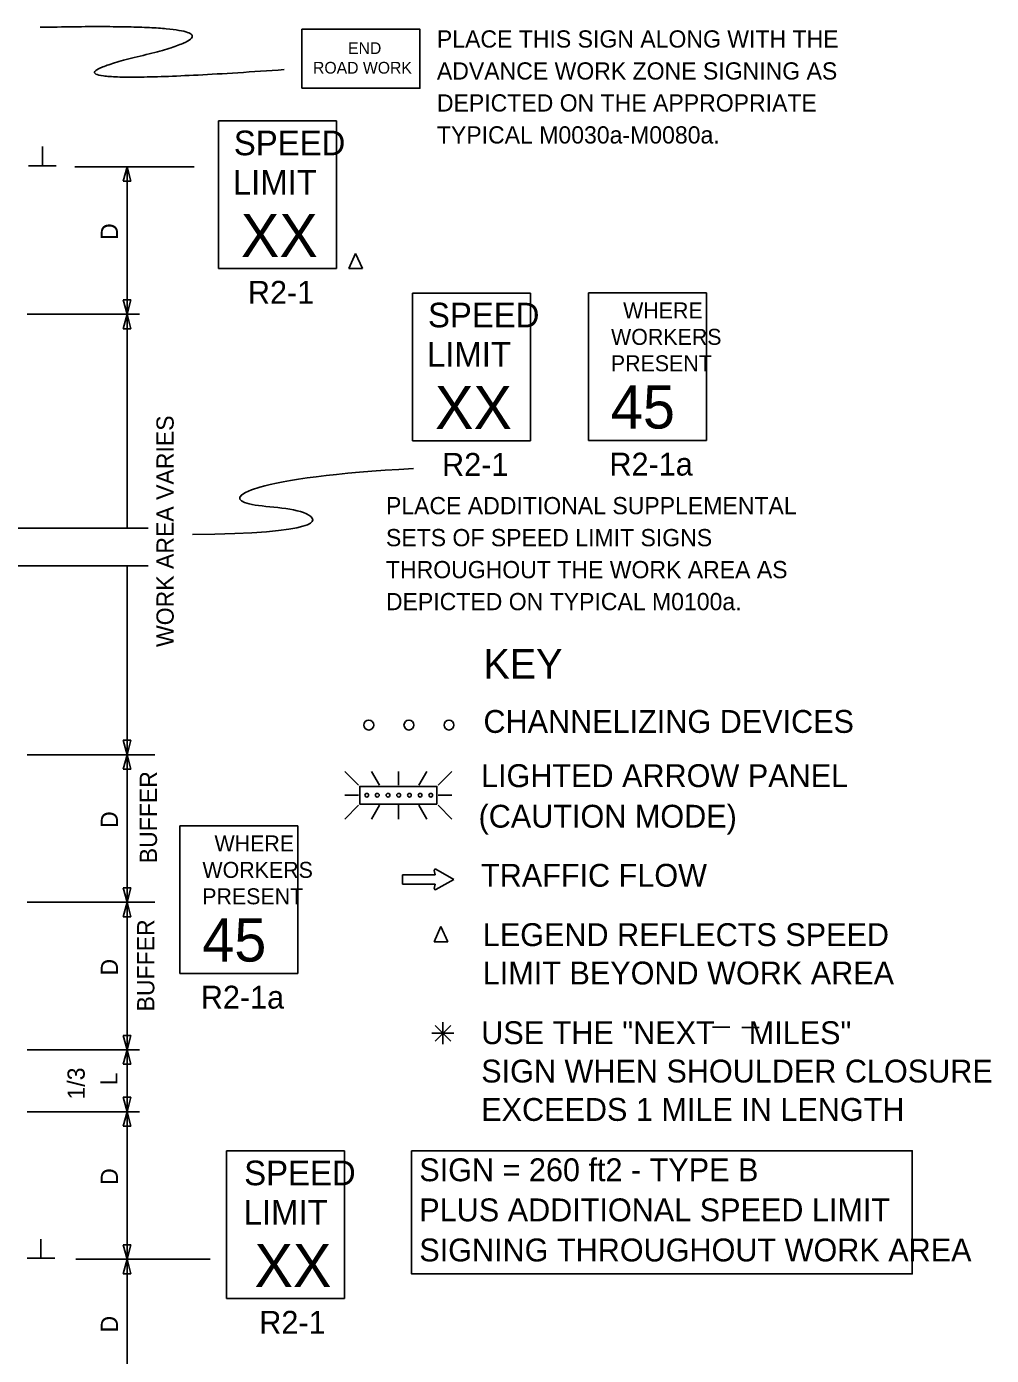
# Model space of a CAD drawing. Extents: x 16730 to 18471, y 6979 to 8225.
# Drawn here: x 17053 to 17445, y 7668 to 8208 of the extents above; entities that cross this region are included whole.
import ezdxf

# ---------------------------------------------------------------- set-up
doc = ezdxf.new("R2010")
doc.units = 0
for name, color, linetype in [('MT_SCRATCH_LEVEL_E', 7, 'Continuous'), ('TRAFFIC_SIGNS_PR', 7, 'Continuous'), ('TYPICAL_EX', 7, 'Continuous'), ('TYPICAL_TEXT_DIMEN_EX', 7, 'Continuous'), ('TYPICAL_TEXT_DIMEN_PR', 7, 'Continuous')]:
    doc.layers.add(name, color=color, linetype=linetype)

msp = doc.modelspace()

# ---------------------------------------------------------------- linework, layer by layer
at = {"layer": 'MT_SCRATCH_LEVEL_E'}
for p, q in [((17218.87, 7863.13), (17205.61, 7863.13)), ((17205.61, 7863.13), (17205.61, 7859.39)), ((17218.87, 7863.13), (17205.61, 7863.13)), ((17205.61, 7863.13), (17205.61, 7859.39)), ((17218.55, 7864.91), (17218.87, 7863.13)), ((17218.55, 7864.91), (17218.87, 7863.13)), ((17226.48, 7861.28), (17219.24, 7865.39)), ((17226.48, 7861.28), (17219.24, 7865.39)), ((17219.24, 7857.14), (17226.48, 7861.28)), ((17219.24, 7857.14), (17226.48, 7861.28)), ((17205.61, 7859.39), (17218.87, 7859.39)), ((17205.61, 7859.39), (17218.87, 7859.39)), ((17218.87, 7859.39), (17218.55, 7857.62)), ((17218.87, 7859.39), (17218.55, 7857.62))]:
    msp.add_line(p, q, dxfattribs=at)
for centre, start, end in [((17219.01, 7864.99), 60.4248, 189.9638), ((17219.01, 7864.99), 60.4248, 189.9638), ((17219.01, 7857.55), 170.0362, 299.7731), ((17219.01, 7857.55), 170.0362, 299.7731)]:
    msp.add_arc(centre, 0.463, start, end, dxfattribs=at)
at = {"layer": 'TRAFFIC_SIGNS_PR'}
for p, q in [((17130.75, 8169.59), (17178.75, 8169.59)), ((17130.75, 8109.59), (17130.75, 8169.59)), ((17178.75, 8109.59), (17178.75, 8169.59)), ((17130.75, 8109.59), (17178.75, 8109.59)), ((17209.69, 8099.63), (17257.69, 8099.63)), ((17209.69, 8039.63), (17209.69, 8099.63)), ((17257.69, 8039.63), (17257.69, 8099.63)), ((17281.19, 8099.74), (17329.19, 8099.74)), ((17281.19, 8039.74), (17281.19, 8099.74)), ((17329.19, 8039.74), (17329.19, 8099.74)), ((17209.69, 8039.63), (17257.69, 8039.63)), ((17281.19, 8039.74), (17329.19, 8039.74)), ((17182.12, 7905.19), (17187.76, 7899.55)), ((17196.3, 7899.55), (17193.04, 7905.19)), ((17203.93, 7899.55), (17203.93, 7905.19)), ((17212.2, 7899.55), (17215.46, 7905.19)), ((17220.1, 7899.55), (17225.74, 7905.2)), ((17187.76, 7895.49), (17182.12, 7895.49)), ((17191.03, 7895.49), (17191.03, 7895.49)), ((17195.38, 7895.49), (17195.38, 7895.49)), ((17199.73, 7895.49), (17199.73, 7895.49)), ((17204.08, 7895.49), (17204.08, 7895.49)), ((17208.42, 7895.49), (17208.42, 7895.49)), ((17212.77, 7895.49), (17212.77, 7895.49)), ((17217.12, 7895.49), (17217.12, 7895.49)), ((17220.1, 7895.49), (17225.74, 7895.49)), ((17182.12, 7885.79), (17187.76, 7891.43)), ((17192.99, 7885.79), (17196.25, 7891.43)), ((17203.93, 7891.43), (17203.93, 7885.79)), ((17215.51, 7885.79), (17212.25, 7891.43)), ((17220.1, 7891.43), (17225.74, 7885.78)), ((17115.04, 7883.05), (17163.04, 7883.05)), ((17115.04, 7823.05), (17115.04, 7883.05)), ((17163.04, 7823.05), (17163.04, 7883.05)), ((17115.04, 7823.05), (17163.04, 7823.05)), ((17134.04, 7750.86), (17182.04, 7750.86)), ((17134.04, 7690.86), (17134.04, 7750.86)), ((17182.04, 7690.86), (17182.04, 7750.86)), ((17134.04, 7690.86), (17182.04, 7690.86))]:
    msp.add_line(p, q, dxfattribs=at)
for points in [[(17164.73, 8182.91), (17212.73, 8182.91), (17212.73, 8206.91), (17164.73, 8206.91)], [(17219.64, 7891.89), (17188.22, 7891.89), (17188.22, 7899.09), (17219.64, 7899.09)]]:
    msp.add_lwpolyline(points, close=True, dxfattribs=at)
for points in [[(17186.57, 8115.76), (17183.77, 8109.59)], [(17183.77, 8109.59), (17186.57, 8115.76)], [(17189.36, 8109.59), (17186.57, 8115.76)], [(17186.57, 8115.76), (17189.36, 8109.59)], [(17183.77, 8109.59), (17189.36, 8109.59)], [(17189.36, 8109.59), (17183.77, 8109.59)], [(17221.24, 7842.11), (17218.45, 7835.94)], [(17218.45, 7835.94), (17221.24, 7842.11)], [(17224.04, 7835.94), (17221.24, 7842.11)], [(17221.24, 7842.11), (17224.04, 7835.94)], [(17218.45, 7835.94), (17224.04, 7835.94)], [(17224.04, 7835.94), (17218.45, 7835.94)]]:
    msp.add_lwpolyline(points, dxfattribs=at)
for centre, radius in [((17191.92, 7924.01), 2), ((17208.22, 7924.01), 2), ((17224.52, 7924.01), 2), ((17191.07, 7895.49), 0.758), ((17195.38, 7895.49), 0.758), ((17199.73, 7895.49), 0.758), ((17204.08, 7895.49), 0.758), ((17208.42, 7895.49), 0.758), ((17212.77, 7895.49), 0.758), ((17217.12, 7895.49), 0.758)]:
    msp.add_circle(centre, radius, dxfattribs=at)
msp.add_open_spline([(17157.52, 8190.49), (17042.3, 8182.26), (17156.21, 8209.84), (17058.26, 8207.67)], degree=2, dxfattribs=at)
at = {"layer": 'TYPICAL_EX'}
for p, q in [((17022.9, 8004.01), (17102.17, 8004.01)), ((17022.9, 7988.69), (17102.17, 7988.69))]:
    msp.add_line(p, q, dxfattribs=at)
at = {"layer": 'TYPICAL_TEXT_DIMEN_EX'}
for p, q in [((17331.67, 7801.26), (17338.67, 7801.26)), ((17343.62, 7801.1), (17350.62, 7801.1))]:
    msp.add_line(p, q, dxfattribs=at)
msp.add_lwpolyline([(17209.32, 7750.98), (17412.91, 7750.98), (17412.91, 7700.91), (17209.32, 7700.91)], close=True, dxfattribs=at)
at = {"layer": 'TYPICAL_TEXT_DIMEN_PR'}
for p, q in [((17059.24, 8151.43), (17059.24, 8159.21)), ((17064.86, 8151.43), (17053.61, 8151.43)), ((17072.45, 8151), (17120.85, 8151)), ((17092.08, 8145.14), (17093.65, 8151)), ((17093.65, 8151), (17093.65, 8091)), ((17093.65, 8151), (17095.22, 8145.14)), ((17093.65, 8145.14), (17092.08, 8145.14)), ((17095.22, 8145.14), (17093.65, 8145.14)), ((17093.65, 8091), (17092.08, 8096.86)), ((17092.08, 8096.86), (17093.65, 8096.86)), ((17093.65, 8096.86), (17095.22, 8096.86)), ((17095.22, 8096.86), (17093.65, 8091)), ((17052.95, 8091), (17098.65, 8091)), ((17092.08, 8085.14), (17093.65, 8091)), ((17093.65, 8091), (17095.22, 8085.14)), ((17093.65, 8091), (17093.65, 8003.81)), ((17093.65, 8085.14), (17092.08, 8085.14)), ((17095.22, 8085.14), (17093.65, 8085.14)), ((17093.65, 7988.65), (17093.65, 7911.96)), ((17093.65, 7911.96), (17092.08, 7917.82)), ((17092.08, 7917.82), (17093.65, 7917.82)), ((17093.65, 7917.82), (17095.22, 7917.82)), ((17095.22, 7917.82), (17093.65, 7911.96)), ((17052.98, 7911.96), (17104.89, 7911.96)), ((17092.08, 7906.1), (17093.65, 7911.96)), ((17093.65, 7911.96), (17093.65, 7851.96)), ((17093.65, 7911.96), (17095.22, 7906.1)), ((17093.65, 7906.1), (17092.08, 7906.1)), ((17095.22, 7906.1), (17093.65, 7906.1)), ((17093.65, 7851.96), (17092.08, 7857.82)), ((17092.08, 7857.82), (17093.65, 7857.82)), ((17093.65, 7857.82), (17095.22, 7857.82)), ((17095.22, 7857.82), (17093.65, 7851.96)), ((17052.98, 7851.96), (17104.89, 7851.96)), ((17092.08, 7846.1), (17093.65, 7851.96)), ((17093.65, 7851.96), (17093.65, 7791.96)), ((17093.65, 7851.96), (17095.22, 7846.1)), ((17093.65, 7846.1), (17092.08, 7846.1)), ((17095.22, 7846.1), (17093.65, 7846.1)), ((17218.84, 7801.93), (17225.22, 7795.56)), ((17225.22, 7801.93), (17218.84, 7795.56)), ((17222.03, 7798.75), (17222.03, 7803.2)), ((17093.65, 7791.96), (17092.08, 7797.82)), ((17092.08, 7797.82), (17093.65, 7797.82)), ((17093.65, 7797.82), (17095.22, 7797.82)), ((17095.22, 7797.82), (17093.65, 7791.96)), ((17222.03, 7798.75), (17217.5, 7798.75)), ((17222.03, 7798.75), (17225.22, 7798.75)), ((17222.03, 7798.75), (17226.51, 7798.75)), ((17222.03, 7798.75), (17222.03, 7794.25)), ((17052.95, 7791.96), (17098.65, 7791.96)), ((17092.08, 7786.1), (17093.65, 7791.96)), ((17093.65, 7791.96), (17093.65, 7766.83)), ((17093.65, 7791.96), (17095.22, 7786.1)), ((17093.65, 7786.1), (17092.08, 7786.1)), ((17095.22, 7786.1), (17093.65, 7786.1)), ((17093.65, 7766.83), (17092.08, 7772.7)), ((17092.08, 7772.7), (17093.65, 7772.7)), ((17093.65, 7772.7), (17095.22, 7772.7)), ((17095.22, 7772.7), (17093.65, 7766.83)), ((17052.95, 7766.83), (17098.65, 7766.83)), ((17092.08, 7760.97), (17093.65, 7766.83)), ((17093.65, 7766.83), (17093.65, 7706.83)), ((17093.65, 7766.83), (17095.22, 7760.97)), ((17093.65, 7760.97), (17092.08, 7760.97)), ((17095.22, 7760.97), (17093.65, 7760.97)), ((17058.58, 7707.26), (17058.58, 7715.05)), ((17093.65, 7706.83), (17092.08, 7712.7)), ((17092.08, 7712.7), (17093.65, 7712.7)), ((17093.65, 7712.7), (17095.22, 7712.7)), ((17095.22, 7712.7), (17093.65, 7706.83)), ((17064.21, 7707.26), (17052.96, 7707.26)), ((17072.81, 7706.83), (17127.44, 7706.83)), ((17092.08, 7700.97), (17093.65, 7706.83)), ((17093.65, 7706.83), (17093.65, 7646.83)), ((17093.65, 7706.83), (17095.22, 7700.97)), ((17093.65, 7700.97), (17092.08, 7700.97)), ((17095.22, 7700.97), (17093.65, 7700.97))]:
    msp.add_line(p, q, dxfattribs=at)
msp.add_open_spline([(17120.18, 8001.48), (17172.4, 8001.84), (17172.4, 8012.59), (17137.49, 8012.59), (17137.49, 8020.44), (17177.93, 8026.69), (17210.03, 8028.27)], degree=3, dxfattribs=at)

# ---------------------------------------------------------------- texts
at = {"layer": 'TRAFFIC_SIGNS_PR'}
for s, height, p in [('PLACE THIS SIGN ALONG WITH THE', 7, (17219.61, 8199.44)), ('END', 4.789, (17183.48, 8196.82)), ('ROAD WORK', 4.789, (17169.24, 8188.84)), ('ADVANCE WORK ZONE SIGNING AS', 7, (17219.61, 8186.44)), ('DEPICTED ON THE APPROPRIATE', 7, (17219.61, 8173.44)), ('SPEED', 10, (17137.04, 8155.67)), ('TYPICAL M0030a-M0080a.', 7, (17219.61, 8160.44)), ('LIMIT', 10, (17136.63, 8139.67)), ('XX', 17.538, (17139.89, 8114.29)), ('R2-1', 9.3, (17142.76, 8095.29)), ('SPEED', 10, (17215.98, 8085.71)), ('WHERE', 6.5, (17295.33, 8089.34)), ('WORKERS', 6.5, (17290.42, 8078.59)), ('LIMIT', 10, (17215.57, 8069.71)), ('PRESENT', 6.5, (17290.33, 8067.84)), ('XX', 17.538, (17218.83, 8044.33)), ('45', 17.538, (17290.32, 8044.56)), ('R2-1', 9.3, (17221.71, 8025.33)), ('R2-1a', 9.3, (17289.76, 8025.44)), ('PLACE ADDITIONAL SUPPLEMENTAL', 7, (17198.89, 8009.72)), ('SETS OF SPEED LIMIT SIGNS', 7, (17198.89, 7996.72)), ('THROUGHOUT THE WORK AREA AS', 7, (17198.89, 7983.72)), ('DEPICTED ON TYPICAL M0100a.', 7, (17198.89, 7970.72)), ('WHERE', 6.5, (17129.18, 7872.65)), ('WORKERS', 6.5, (17124.27, 7861.9)), ('PRESENT', 6.5, (17124.18, 7851.15)), ('45', 17.538, (17124.17, 7827.87)), ('R2-1a', 9.3, (17123.61, 7808.75)), ('SPEED', 10, (17141.25, 7736.94)), ('LIMIT', 10, (17141.05, 7720.94)), ('XX', 17.538, (17145.43, 7695.56)), ('R2-1', 9.3, (17147.39, 7676.56))]:
    msp.add_text(s, height=height, dxfattribs=at).set_placement(p)
at = {"layer": 'TYPICAL_TEXT_DIMEN_EX'}
for s, height, p in [('KEY', 12, (17238.54, 7942.89)), ('CHANNELIZING DEVICES', 9.3, (17238.54, 7920.84)), ('LIGHTED ARROW PANEL', 9.3, (17237.55, 7898.79)), ('(CAUTION MODE)', 9.3, (17236.55, 7882.3)), ('TRAFFIC FLOW', 9.3, (17237.55, 7858.29)), ('LEGEND REFLECTS SPEED', 9.3, (17238.27, 7834.16)), ('LIMIT BEYOND WORK AREA', 9.3, (17238.27, 7818.56)), ('USE THE "NEXT    MILES"', 9.3, (17237.63, 7794.3)), ('SIGN WHEN SHOULDER CLOSURE', 9.3, (17237.63, 7778.7)), ('EXCEEDS 1 MILE IN LENGTH', 9.3, (17237.63, 7763.1)), ('SIGN = 260 ft2 - TYPE B', 9.3, (17212.45, 7738.57)), ('PLUS ADDITIONAL SPEED LIMIT', 9.3, (17212.45, 7722.27)), ('SIGNING THROUGHOUT WORK AREA', 9.3, (17212.45, 7705.97))]:
    msp.add_text(s, height=height, dxfattribs=at).set_placement(p)
at = {"layer": 'TYPICAL_TEXT_DIMEN_PR'}
for s, p in [('D', (17089.92, 8121.24)), ('WORK AREA VARIES', (17112.58, 7955.74)), ('BUFFER', (17105.79, 7867.84)), ('D', (17089.92, 7882.2)), ('BUFFER', (17104.71, 7807.6)), ('D', (17089.92, 7822.2)), ('1/3', (17076.41, 7771.78)), ('L', (17089.71, 7777.57)), ('D', (17089.92, 7737.08)), ('D', (17089.92, 7677.08))]:
    msp.add_text(s, height=7, rotation=90, dxfattribs=at).set_placement(p)

doc.saveas('drawing.dxf')
